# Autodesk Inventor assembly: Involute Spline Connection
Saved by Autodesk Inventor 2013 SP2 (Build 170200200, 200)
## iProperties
Created: 2020-02
Part Number: Involute Spline Connection
Document SubType Name: Assembly
Designer: DELL
ClientObjectVersion: 1
Author: DELL
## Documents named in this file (1)
- C:\Users\DELL\Dropbox\Inventor\Projects\Quadcopter F450\Assemblies\Servo - Design Accelerator Spline Tutorial\Design Accelerator - 5mm Shaft and Spline\Design Accelerator\Involute Spline Connection1.iam
